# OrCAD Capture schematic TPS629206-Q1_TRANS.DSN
size D; title: TPS629206-Q1 3-V to 17-V, 0.6A Low IQ Buck Converter in; rev: 1.0; note: Datasheet: SLVSFS6B     EVM: SLVUCC5; note: Synchronous Step Down Converter
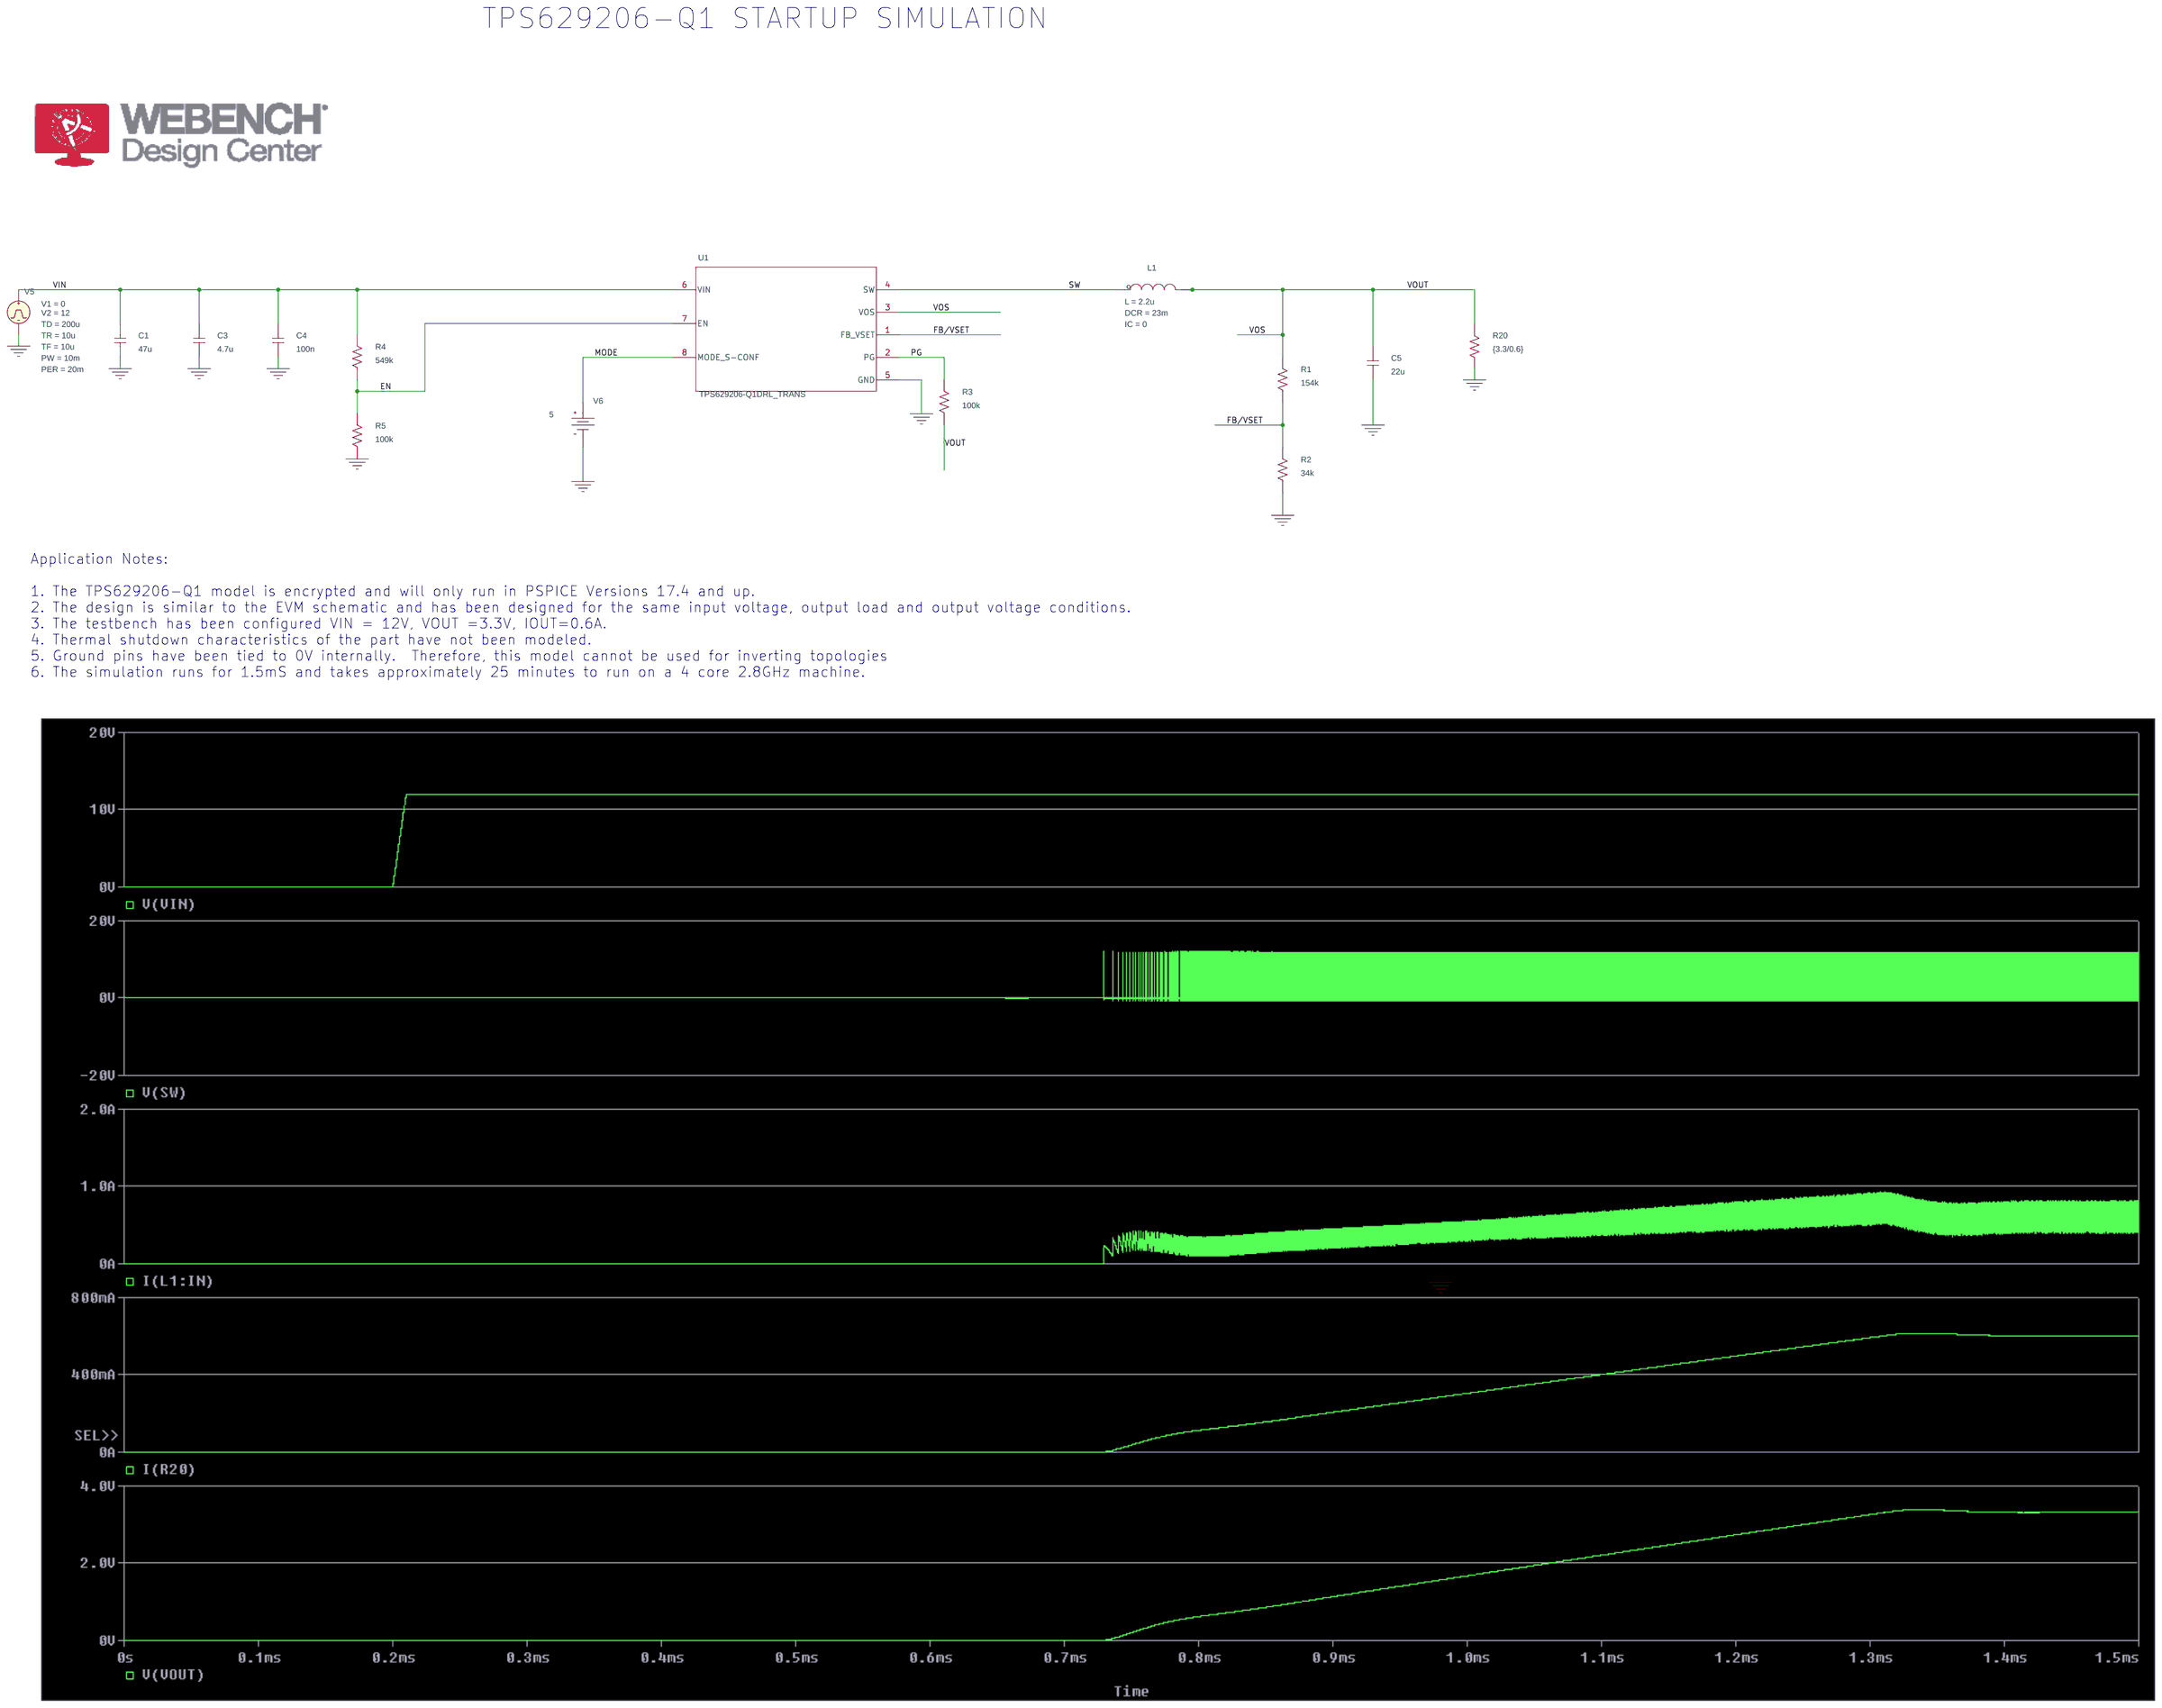
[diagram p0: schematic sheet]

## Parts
C1  47u  [cap196]
C3  4.7u  [cap196]
C4  100n  [cap196]
C5  22u  [cap196]
L1  LDCR
R1  154k  [AXRC05]
R2  34k  [AXRC05]
R3  100k  [AXRC05]
R4  549k  [AXRC05]
R5  100k  [AXRC05]
R20  {3.3/0.6}  [AXRC05]
U1  TPS629206-Q1DRL_TRANS  [DRL0008A-MFG]
V5  VPULSE
V6  VDC

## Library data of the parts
C1 C3-C5 = C
L1 = LDCR_1: DCR: 23m; IC: 0; L: 2.2u; PSpiceTemplate: X^@REFDES %IN %OUT @MODEL PARAMS:  ?L|L=@L||L=1u|  ?DCR|DCR=@DCR||DCR=0.01|  ?IC|IC=@IC||IC=0|
R1-R5 R20 = R
U1 = TPS629206-Q1DRL_TRANS
V5 = VPULSE: PER: 20m; PW: 10m; TD: 200u; TF: 10u; TR: 10u; V1: 0; V2: 12
V6 = VDC: DC: 5

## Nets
VIN: C1.2 C3.2 C4.2 R4.2 U1.6(VIN) V5.1(+)
0: C1.1 C3.1 C4.1 C5.1 R2.1 R5.1 R20.2 U1.5(GND) V5.2(-) V6.1(-)
EN: R4.1 R5.2 U1.7(EN)
FB/VSET: R1.1 R2.2 U1.1(FB_VSET)
MODE: U1.8(MODE_S-CONF) V6.0(+)
PG: R3.2 U1.2(PG)
SW: L1.1(IN) U1.4(SW)
VOS: C5.2 L1.3(OUT) R1.2 R3.1 R20.1 U1.3(VOS)

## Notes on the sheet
- TPS629206-Q1 STARTUP SIMULATION
- Application Notes:
  1. The TPS629206-Q1 model is encrypted and will only run in PSPICE Versions 17.4 and up.
  2. The design is similar to the EVM schematic and has been designed for the same input voltage, output load and output voltage conditions.
  3. The testbench has been configured VIN = 12V, VOUT =3.3V, IOUT=0.6A.
  4. Thermal shutdown characteristics of the part have not been modeled.
  5. Ground pins have been tied to 0V internally.  Therefore, this model cannot be used for inverting topologies
  6. The simulation runs for 1.5mS and takes approximately 25 minutes to run on a 4 core 2.8GHz machine.
